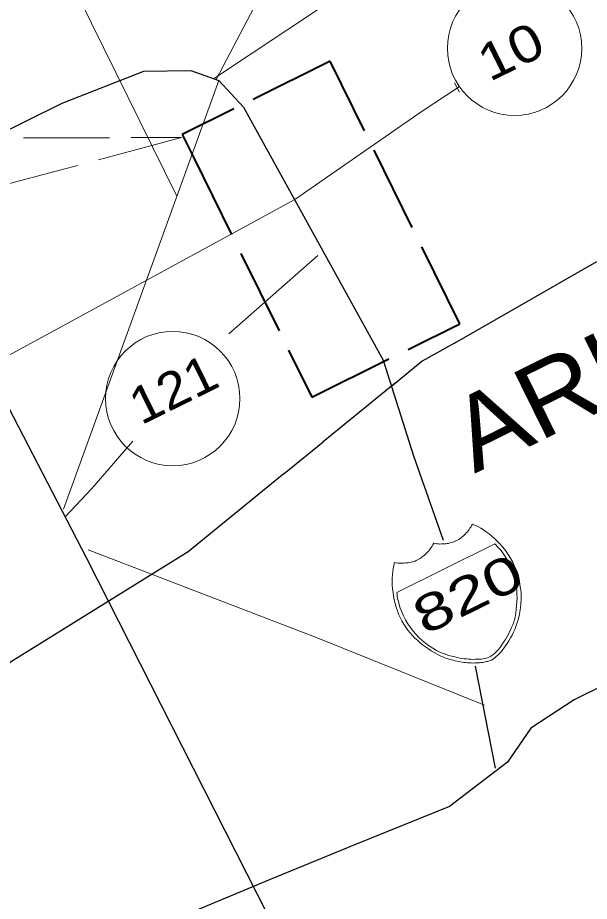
# Model space of a CAD drawing. Extents: x 2356606 to 2371222, y 6973096 to 6982644.
# Drawn here: x 2370898 to 2370977.6, y 6980347 to 6980470.1 of the extents above; entities that cross this region are included whole.
import ezdxf

# ---------------------------------------------------------------- set-up
doc = ezdxf.new("R2010")
doc.units = 0
doc.header["$LTSCALE"] = 2
doc.linetypes.add('LONG_DASHED', pattern=[7.5, 6, -1.5])
doc.layers.add('62', color=7, linetype='Continuous', lineweight=13)
doc.layers.add('63', color=7, linetype='Continuous', lineweight=13)

msp = doc.modelspace()

# ---------------------------------------------------------------- linework, layer by layer
at = {"layer": '62'}
for p, q in [((2370920.14, 6980445.229), (2370900.731, 6980484.556)), ((2370925.98, 6980461.31), (2370904.323, 6980401.619)), ((2370954.344, 6980457.069), (2370959.496, 6980460.463)), ((2370958.814, 6980460.982), (2370959.542, 6980459.711)), ((2370932.403, 6980430.45), (2370939.761, 6980436.945)), ((2370927.387, 6980426.022), (2370932.403, 6980430.45)), ((2370908.276, 6980404.496), (2370913.994, 6980411.055)), ((2370908.276, 6980404.496), (2370904.581, 6980400.541))]:
    msp.add_line(p, q, dxfattribs=at)
at = {"layer": '62', "lineweight": 25}
for p, q in [((2370925.98, 6980461.31), (2370929.431, 6980457.621)), ((2370929.431, 6980457.62), (2370948.893, 6980422.357)), ((2370958.804, 6980424.741), (2370978.671, 6980436.103)), ((2370950.577, 6980419.149), (2370940.532, 6980410.978)), ((2370935.107, 6980406.569), (2370940.532, 6980410.978)), ((2370961.725, 6980379.732), (2370964.509, 6980365.5))]:
    msp.add_line(p, q, dxfattribs=at)
at = {"layer": '62'}
for points in [[(2370938.756, 6980487.894), (2370934.235, 6980477.93), (2370925.608, 6980461.455)], [(2370925.246, 6980461.577), (2370940.846, 6980471.91), (2370955.63, 6980481.415)], [(2370954.344, 6980457.069), (2370936.581, 6980444.761), (2370894.075, 6980421.624), (2370888.003, 6980417.247)], [(2370956.789, 6980396.747), (2370957.012, 6980396.756), (2370957.214, 6980396.753), (2370957.405, 6980396.774), (2370957.626, 6980396.782), (2370957.807, 6980396.822), (2370957.999, 6980396.84), (2370958.202, 6980396.89), (2370958.371, 6980396.949), (2370958.572, 6980396.998), (2370958.753, 6980397.038), (2370958.936, 6980397.128), (2370959.117, 6980397.217), (2370959.259, 6980397.287), (2370959.44, 6980397.377), (2370959.601, 6980397.507), (2370959.743, 6980397.627), (2370959.897, 6980397.726), (2370960.055, 6980397.857), (2370960.189, 6980397.997), (2370960.329, 6980398.116), (2370960.472, 6980398.287), (2370960.623, 6980398.438), (2370960.725, 6980398.588), (2370960.866, 6980398.758), (2370960.978, 6980398.939), (2370961.098, 6980399.101), (2370961.219, 6980399.308), (2370961.342, 6980399.52), (2370961.706, 6980399.348), (2370962.067, 6980399.173), (2370962.478, 6980398.95), (2370962.847, 6980398.707), (2370963.23, 6980398.442), (2370963.641, 6980398.17), (2370964.022, 6980397.855), (2370964.382, 6980397.532), (2370964.772, 6980397.149), (2370965.133, 6980396.774), (2370965.492, 6980396.398), (2370965.823, 6980395.986), (2370966.133, 6980395.561), (2370966.422, 6980395.125), (2370966.682, 6980394.702), (2370966.943, 6980394.228), (2370967.159, 6980393.735), (2370967.378, 6980393.188), (2370967.568, 6980392.654), (2370967.737, 6980392.162), (2370967.874, 6980391.627), (2370967.951, 6980391.064), (2370968.03, 6980390.551), (2370968.097, 6980390.005), (2370968.134, 6980389.473), (2370968.112, 6980388.907), (2370968.088, 6980388.395), (2370968.037, 6980387.84), (2370967.932, 6980387.287), (2370967.839, 6980386.764), (2370967.684, 6980386.213), (2370967.524, 6980385.679), (2370967.367, 6980385.278), (2370967.226, 6980384.855), (2370967.052, 6980384.444), (2370966.868, 6980384.052), (2370966.634, 6980383.66), (2370966.402, 6980383.271), (2370966.179, 6980382.909), (2370965.936, 6980382.539), (2370965.712, 6980382.228), (2370965.469, 6980381.907), (2370965.196, 6980381.597), (2370964.933, 6980381.316), (2370964.699, 6980381.127), (2370964.439, 6980380.895), (2370964.196, 6980380.726), (2370963.962, 6980380.586)], [(2370963.962, 6980380.586), (2370963.793, 6980380.527), (2370963.651, 6980380.457), (2370963.458, 6980380.388), (2370963.299, 6980380.357), (2370963.117, 6980380.32), (2370962.936, 6980380.278), (2370962.724, 6980380.252), (2370962.51, 6980380.221), (2370962.293, 6980380.213), (2370962.08, 6980380.184), (2370961.827, 6980380.185), (2370961.628, 6980380.186), (2370961.385, 6980380.168), (2370961.153, 6980380.177), (2370960.892, 6980380.2), (2370960.661, 6980380.212), (2370960.399, 6980380.233), (2370960.138, 6980380.254), (2370959.888, 6980380.305), (2370959.664, 6980380.347), (2370959.424, 6980380.378), (2370959.143, 6980380.44), (2370958.89, 6980380.492), (2370958.68, 6980380.564), (2370958.408, 6980380.605), (2370958.197, 6980380.676), (2370957.936, 6980380.748), (2370957.726, 6980380.818), (2370957.484, 6980380.902), (2370957.275, 6980380.972), (2370957.072, 6980381.075), (2370956.851, 6980381.167), (2370956.419, 6980381.378), (2370955.977, 6980381.613), (2370955.575, 6980381.868), (2370955.195, 6980382.132), (2370954.784, 6980382.404), (2370954.371, 6980382.68), (2370954.02, 6980382.984), (2370953.652, 6980383.328), (2370953.301, 6980383.632), (2370952.961, 6980384.018), (2370952.65, 6980384.391), (2370952.341, 6980384.764), (2370952.039, 6980385.169), (2370951.781, 6980385.591), (2370951.502, 6980386.057), (2370951.261, 6980386.491), (2370951.043, 6980386.983), (2370950.865, 6980387.448), (2370950.697, 6980387.941), (2370950.568, 6980388.457), (2370950.422, 6980388.96), (2370950.343, 6980389.472), (2370950.263, 6980389.986), (2370950.178, 6980390.522), (2370950.16, 6980391.014), (2370950.142, 6980391.507), (2370950.152, 6980391.988), (2370950.196, 6980392.463), (2370950.249, 6980392.916), (2370950.281, 6980393.358), (2370950.386, 6980393.76), (2370950.468, 6980394.153), (2370950.709, 6980394.122), (2370950.95, 6980394.09), (2370951.152, 6980394.087), (2370951.362, 6980394.069), (2370951.583, 6980394.077), (2370951.785, 6980394.076), (2370951.998, 6980394.105), (2370952.219, 6980394.114), (2370952.38, 6980394.143), (2370952.591, 6980394.173), (2370952.773, 6980394.211), (2370952.962, 6980394.28), (2370953.165, 6980394.33), (2370953.347, 6980394.367), (2370953.507, 6980394.449), (2370953.691, 6980394.537), (2370953.852, 6980394.619), (2370954.033, 6980394.708), (2370954.176, 6980394.829), (2370954.337, 6980394.956), (2370954.468, 6980395.048), (2370954.629, 6980395.176), (2370954.78, 6980395.327), (2370954.943, 6980395.458), (2370955.043, 6980395.608), (2370955.195, 6980395.76), (2370955.337, 6980395.929), (2370955.459, 6980396.09), (2370955.573, 6980396.269), (2370955.712, 6980396.44), (2370955.796, 6980396.631), (2370955.935, 6980396.851), (2370956.136, 6980396.8), (2370956.357, 6980396.759), (2370956.578, 6980396.767), (2370956.789, 6980396.747)], [(2370962.995, 6980374.312), (2370939.686, 6980383.663), (2370907.798, 6980395.952)]]:
    msp.add_lwpolyline(points, dxfattribs=at)
at = {"layer": '62', "linetype": 'LONG_DASHED', "lineweight": 40}
msp.add_lwpolyline([(2370922.432, 6980450.654), (2370938.933, 6980417.218), (2370959.577, 6980427.404), (2370941.512, 6980464.007), (2370920.869, 6980453.821)], close=True, dxfattribs=at)
at = {"layer": '62', "lineweight": 25}
for points in [[(2370836.799, 6980393.483), (2370842.869, 6980403.757), (2370853.379, 6980414.24), (2370860.236, 6980422.918), (2370867.185, 6980431.465), (2370875.952, 6980441.111), (2370880.901, 6980446.691), (2370889.861, 6980451.112), (2370904.166, 6980458.172), (2370915.531, 6980462.603), (2370922.103, 6980462.709), (2370925.98, 6980461.31)], [(2370885.051, 6980438.124), (2370907.53, 6980394.764), (2370932.824, 6980345.045), (2370969.992, 6980283.97), (2370998.654, 6980263.059)], [(2370958.804, 6980424.741), (2370954.315, 6980422.2), (2370950.041, 6980418.709)], [(2370948.893, 6980422.358), (2370953.121, 6980409.011), (2370957.257, 6980397.276)], [(2370935.107, 6980406.569), (2370921.734, 6980395.679), (2370896.929, 6980380.299), (2370879.573, 6980365.436), (2370873.619, 6980362.044)], [(2371011.483, 6980396.661), (2371005.138, 6980391.825), (2370996.569, 6980386.616), (2370984.445, 6980379.452), (2370975.486, 6980375.033), (2370969.457, 6980371.078), (2370966.224, 6980366.347), (2370958.11, 6980360.159), (2370945.05, 6980354.893), (2370933.131, 6980350.014), (2370920.141, 6980344.556), (2370901.53, 6980332.234), (2370881.498, 6980325.485), (2370864.621, 6980321.497), (2370853.225, 6980321.969), (2370844.613, 6980332.451), (2370838.758, 6980344.313), (2370834.175, 6980349.329), (2370834.503, 6980359.904)]]:
    msp.add_lwpolyline(points, dxfattribs=at)
at = {"layer": '62', "linetype": 'LONG_DASHED'}
for points in [[(2370853.763, 6980453.224), (2370920.786, 6980453.379), (2370861.241, 6980437.463)], [(2370853.763, 6980453.224), (2370920.786, 6980453.379), (2370861.241, 6980437.463), (2370853.763, 6980453.224)]]:
    msp.add_lwpolyline(points, close=True, dxfattribs=at)
at = {"layer": '62'}
msp.add_lwpolyline([(2370964.439, 6980396.757), (2370950.778, 6980390.014), (2370950.814, 6980389.783), (2370950.843, 6980389.471), (2370950.904, 6980389.149), (2370951.023, 6980388.755), (2370951.121, 6980388.303), (2370951.248, 6980387.787), (2370951.467, 6980387.295), (2370951.726, 6980386.72), (2370952.016, 6980386.183), (2370952.323, 6980385.61), (2370952.694, 6980385.115), (2370953.064, 6980384.619), (2370953.474, 6980384.145), (2370953.875, 6980383.74), (2370954.344, 6980383.295), (2370954.807, 6980382.922), (2370955.28, 6980382.574), (2370955.788, 6980382.248), (2370956.325, 6980381.933), (2370956.866, 6980381.651), (2370957.447, 6980381.436), (2370958.05, 6980381.232), (2370958.651, 6980381.076), (2370959.275, 6980380.932), (2370959.546, 6980380.84), (2370959.859, 6980380.819), (2370960.191, 6980380.757), (2370960.503, 6980380.736), (2370960.794, 6980380.702), (2370961.105, 6980380.681), (2370961.407, 6980380.68), (2370961.73, 6980380.689), (2370962.002, 6980380.698), (2370962.273, 6980380.706), (2370962.565, 6980380.723), (2370962.827, 6980380.753), (2370963.08, 6980380.802), (2370963.3, 6980380.862), (2370963.53, 6980380.951), (2370963.745, 6980381.031), (2370964.007, 6980381.208), (2370964.329, 6980381.42), (2370964.573, 6980381.69), (2370964.897, 6980382.001), (2370965.15, 6980382.3), (2370965.413, 6980382.681), (2370965.677, 6980383.063), (2370965.92, 6980383.435), (2370966.185, 6980383.864), (2370966.378, 6980384.287), (2370966.581, 6980384.689), (2370966.775, 6980385.109), (2370966.957, 6980385.5), (2370967.079, 6980385.862), (2370967.191, 6980386.245), (2370967.265, 6980386.556), (2370967.357, 6980387.129), (2370967.441, 6980387.674), (2370967.484, 6980388.197), (2370967.517, 6980388.739), (2370967.549, 6980389.235), (2370967.531, 6980389.728), (2370967.523, 6980390.201), (2370967.465, 6980390.674), (2370967.408, 6980391.148), (2370967.329, 6980391.56), (2370967.231, 6980392.012), (2370967.083, 6980392.415), (2370966.952, 6980392.83), (2370966.805, 6980393.232), (2370966.636, 6980393.625), (2370966.476, 6980393.998), (2370966.177, 6980394.555), (2370965.898, 6980395.02), (2370965.589, 6980395.443), (2370965.348, 6980395.826), (2370965.071, 6980396.141), (2370964.829, 6980396.372), (2370964.619, 6980396.594)], close=True, dxfattribs=at)
for centre in [(2370967.199, 6980465.817), (2370919.564, 6980417.013)]:
    msp.add_circle(centre, 9.364, dxfattribs=at)
at = {"layer": '63'}
for p, q in [((2370920.14, 6980445.229), (2370900.731, 6980484.556)), ((2370925.98, 6980461.31), (2370904.323, 6980401.619)), ((2370954.344, 6980457.069), (2370959.496, 6980460.463)), ((2370958.814, 6980460.982), (2370959.542, 6980459.711)), ((2370932.403, 6980430.45), (2370939.761, 6980436.945)), ((2370927.387, 6980426.022), (2370932.403, 6980430.45)), ((2370908.276, 6980404.496), (2370913.994, 6980411.055)), ((2370908.276, 6980404.496), (2370904.581, 6980400.541))]:
    msp.add_line(p, q, dxfattribs=at)
at = {"layer": '63', "lineweight": 25}
for p, q in [((2370925.98, 6980461.31), (2370929.431, 6980457.621)), ((2370929.431, 6980457.62), (2370948.893, 6980422.357)), ((2370958.804, 6980424.741), (2370978.671, 6980436.103)), ((2370950.577, 6980419.149), (2370940.532, 6980410.978)), ((2370935.107, 6980406.569), (2370940.532, 6980410.978)), ((2370961.725, 6980379.732), (2370964.509, 6980365.5))]:
    msp.add_line(p, q, dxfattribs=at)
at = {"layer": '63'}
for points in [[(2370938.756, 6980487.894), (2370934.235, 6980477.93), (2370925.608, 6980461.455)], [(2370925.246, 6980461.577), (2370940.846, 6980471.91), (2370955.63, 6980481.415)], [(2370954.344, 6980457.069), (2370936.581, 6980444.761), (2370894.075, 6980421.624), (2370888.003, 6980417.247)], [(2370956.789, 6980396.747), (2370957.012, 6980396.756), (2370957.214, 6980396.753), (2370957.405, 6980396.774), (2370957.626, 6980396.782), (2370957.807, 6980396.822), (2370957.999, 6980396.84), (2370958.202, 6980396.89), (2370958.371, 6980396.949), (2370958.572, 6980396.998), (2370958.753, 6980397.038), (2370958.936, 6980397.128), (2370959.117, 6980397.217), (2370959.259, 6980397.287), (2370959.44, 6980397.377), (2370959.601, 6980397.507), (2370959.743, 6980397.627), (2370959.897, 6980397.726), (2370960.055, 6980397.857), (2370960.189, 6980397.997), (2370960.329, 6980398.116), (2370960.472, 6980398.287), (2370960.623, 6980398.438), (2370960.725, 6980398.588), (2370960.866, 6980398.758), (2370960.978, 6980398.939), (2370961.098, 6980399.101), (2370961.219, 6980399.308), (2370961.342, 6980399.52), (2370961.706, 6980399.348), (2370962.067, 6980399.173), (2370962.478, 6980398.95), (2370962.847, 6980398.707), (2370963.23, 6980398.442), (2370963.641, 6980398.17), (2370964.022, 6980397.855), (2370964.382, 6980397.532), (2370964.772, 6980397.149), (2370965.133, 6980396.774), (2370965.492, 6980396.398), (2370965.823, 6980395.986), (2370966.133, 6980395.561), (2370966.422, 6980395.125), (2370966.682, 6980394.702), (2370966.943, 6980394.228), (2370967.159, 6980393.735), (2370967.378, 6980393.188), (2370967.568, 6980392.654), (2370967.737, 6980392.162), (2370967.874, 6980391.627), (2370967.951, 6980391.064), (2370968.03, 6980390.551), (2370968.097, 6980390.005), (2370968.134, 6980389.473), (2370968.112, 6980388.907), (2370968.088, 6980388.395), (2370968.037, 6980387.84), (2370967.932, 6980387.287), (2370967.839, 6980386.764), (2370967.684, 6980386.213), (2370967.524, 6980385.679), (2370967.367, 6980385.278), (2370967.226, 6980384.855), (2370967.052, 6980384.444), (2370966.868, 6980384.052), (2370966.634, 6980383.66), (2370966.402, 6980383.271), (2370966.179, 6980382.909), (2370965.936, 6980382.539), (2370965.712, 6980382.228), (2370965.469, 6980381.907), (2370965.196, 6980381.597), (2370964.933, 6980381.316), (2370964.699, 6980381.127), (2370964.439, 6980380.895), (2370964.196, 6980380.726), (2370963.962, 6980380.586)], [(2370963.962, 6980380.586), (2370963.793, 6980380.527), (2370963.651, 6980380.457), (2370963.458, 6980380.388), (2370963.299, 6980380.357), (2370963.117, 6980380.32), (2370962.936, 6980380.278), (2370962.724, 6980380.252), (2370962.51, 6980380.221), (2370962.293, 6980380.213), (2370962.08, 6980380.184), (2370961.827, 6980380.185), (2370961.628, 6980380.186), (2370961.385, 6980380.168), (2370961.153, 6980380.177), (2370960.892, 6980380.2), (2370960.661, 6980380.212), (2370960.399, 6980380.233), (2370960.138, 6980380.254), (2370959.888, 6980380.305), (2370959.664, 6980380.347), (2370959.424, 6980380.378), (2370959.143, 6980380.44), (2370958.89, 6980380.492), (2370958.68, 6980380.564), (2370958.408, 6980380.605), (2370958.197, 6980380.676), (2370957.936, 6980380.748), (2370957.726, 6980380.818), (2370957.484, 6980380.902), (2370957.275, 6980380.972), (2370957.072, 6980381.075), (2370956.851, 6980381.167), (2370956.419, 6980381.378), (2370955.977, 6980381.613), (2370955.575, 6980381.868), (2370955.195, 6980382.132), (2370954.784, 6980382.404), (2370954.371, 6980382.68), (2370954.02, 6980382.984), (2370953.652, 6980383.328), (2370953.301, 6980383.632), (2370952.961, 6980384.018), (2370952.65, 6980384.391), (2370952.341, 6980384.764), (2370952.039, 6980385.169), (2370951.781, 6980385.591), (2370951.502, 6980386.057), (2370951.261, 6980386.491), (2370951.043, 6980386.983), (2370950.865, 6980387.448), (2370950.697, 6980387.941), (2370950.568, 6980388.457), (2370950.422, 6980388.96), (2370950.343, 6980389.472), (2370950.263, 6980389.986), (2370950.178, 6980390.522), (2370950.16, 6980391.014), (2370950.142, 6980391.507), (2370950.152, 6980391.988), (2370950.196, 6980392.463), (2370950.249, 6980392.916), (2370950.281, 6980393.358), (2370950.386, 6980393.76), (2370950.468, 6980394.153), (2370950.709, 6980394.122), (2370950.95, 6980394.09), (2370951.152, 6980394.087), (2370951.362, 6980394.069), (2370951.583, 6980394.077), (2370951.785, 6980394.076), (2370951.998, 6980394.105), (2370952.219, 6980394.114), (2370952.38, 6980394.143), (2370952.591, 6980394.173), (2370952.773, 6980394.211), (2370952.962, 6980394.28), (2370953.165, 6980394.33), (2370953.347, 6980394.367), (2370953.507, 6980394.449), (2370953.691, 6980394.537), (2370953.852, 6980394.619), (2370954.033, 6980394.708), (2370954.176, 6980394.829), (2370954.337, 6980394.956), (2370954.468, 6980395.048), (2370954.629, 6980395.176), (2370954.78, 6980395.327), (2370954.943, 6980395.458), (2370955.043, 6980395.608), (2370955.195, 6980395.76), (2370955.337, 6980395.929), (2370955.459, 6980396.09), (2370955.573, 6980396.269), (2370955.712, 6980396.44), (2370955.796, 6980396.631), (2370955.935, 6980396.851), (2370956.136, 6980396.8), (2370956.357, 6980396.759), (2370956.578, 6980396.767), (2370956.789, 6980396.747)], [(2370962.995, 6980374.312), (2370939.686, 6980383.663), (2370907.798, 6980395.952)]]:
    msp.add_lwpolyline(points, dxfattribs=at)
at = {"layer": '63', "linetype": 'LONG_DASHED', "lineweight": 40}
msp.add_lwpolyline([(2370922.432, 6980450.654), (2370938.933, 6980417.218), (2370959.577, 6980427.404), (2370941.512, 6980464.007), (2370920.869, 6980453.821)], close=True, dxfattribs=at)
at = {"layer": '63', "lineweight": 25}
for points in [[(2370836.799, 6980393.483), (2370842.869, 6980403.757), (2370853.379, 6980414.24), (2370860.236, 6980422.918), (2370867.185, 6980431.465), (2370875.952, 6980441.111), (2370880.901, 6980446.691), (2370889.861, 6980451.112), (2370904.166, 6980458.172), (2370915.531, 6980462.603), (2370922.103, 6980462.709), (2370925.98, 6980461.31)], [(2370885.051, 6980438.124), (2370907.53, 6980394.764), (2370932.824, 6980345.045), (2370969.992, 6980283.97), (2370998.654, 6980263.059)], [(2370958.804, 6980424.741), (2370954.315, 6980422.2), (2370950.041, 6980418.709)], [(2370948.893, 6980422.358), (2370953.121, 6980409.011), (2370957.257, 6980397.276)], [(2370935.107, 6980406.569), (2370921.734, 6980395.679), (2370896.929, 6980380.299), (2370879.573, 6980365.436), (2370873.619, 6980362.044)], [(2371011.483, 6980396.661), (2371005.138, 6980391.825), (2370996.569, 6980386.616), (2370984.445, 6980379.452), (2370975.486, 6980375.033), (2370969.457, 6980371.078), (2370966.224, 6980366.347), (2370958.11, 6980360.159), (2370945.05, 6980354.893), (2370933.131, 6980350.014), (2370920.141, 6980344.556), (2370901.53, 6980332.234), (2370881.498, 6980325.485), (2370864.621, 6980321.497), (2370853.225, 6980321.969), (2370844.613, 6980332.451), (2370838.758, 6980344.313), (2370834.175, 6980349.329), (2370834.503, 6980359.904)]]:
    msp.add_lwpolyline(points, dxfattribs=at)
at = {"layer": '63', "linetype": 'LONG_DASHED'}
for points in [[(2370853.763, 6980453.224), (2370920.786, 6980453.379), (2370861.241, 6980437.463)], [(2370853.763, 6980453.224), (2370920.786, 6980453.379), (2370861.241, 6980437.463), (2370853.763, 6980453.224)]]:
    msp.add_lwpolyline(points, close=True, dxfattribs=at)
at = {"layer": '63'}
msp.add_lwpolyline([(2370964.439, 6980396.757), (2370950.778, 6980390.014), (2370950.814, 6980389.783), (2370950.843, 6980389.471), (2370950.904, 6980389.149), (2370951.023, 6980388.755), (2370951.121, 6980388.303), (2370951.248, 6980387.787), (2370951.467, 6980387.295), (2370951.726, 6980386.72), (2370952.016, 6980386.183), (2370952.323, 6980385.61), (2370952.694, 6980385.115), (2370953.064, 6980384.619), (2370953.474, 6980384.145), (2370953.875, 6980383.74), (2370954.344, 6980383.295), (2370954.807, 6980382.922), (2370955.28, 6980382.574), (2370955.788, 6980382.248), (2370956.325, 6980381.933), (2370956.866, 6980381.651), (2370957.447, 6980381.436), (2370958.05, 6980381.232), (2370958.651, 6980381.076), (2370959.275, 6980380.932), (2370959.546, 6980380.84), (2370959.859, 6980380.819), (2370960.191, 6980380.757), (2370960.503, 6980380.736), (2370960.794, 6980380.702), (2370961.105, 6980380.681), (2370961.407, 6980380.68), (2370961.73, 6980380.689), (2370962.002, 6980380.698), (2370962.273, 6980380.706), (2370962.565, 6980380.723), (2370962.827, 6980380.753), (2370963.08, 6980380.802), (2370963.3, 6980380.862), (2370963.53, 6980380.951), (2370963.745, 6980381.031), (2370964.007, 6980381.208), (2370964.329, 6980381.42), (2370964.573, 6980381.69), (2370964.897, 6980382.001), (2370965.15, 6980382.3), (2370965.413, 6980382.681), (2370965.677, 6980383.063), (2370965.92, 6980383.435), (2370966.185, 6980383.864), (2370966.378, 6980384.287), (2370966.581, 6980384.689), (2370966.775, 6980385.109), (2370966.957, 6980385.5), (2370967.079, 6980385.862), (2370967.191, 6980386.245), (2370967.265, 6980386.556), (2370967.357, 6980387.129), (2370967.441, 6980387.674), (2370967.484, 6980388.197), (2370967.517, 6980388.739), (2370967.549, 6980389.235), (2370967.531, 6980389.728), (2370967.523, 6980390.201), (2370967.465, 6980390.674), (2370967.408, 6980391.148), (2370967.329, 6980391.56), (2370967.231, 6980392.012), (2370967.083, 6980392.415), (2370966.952, 6980392.83), (2370966.805, 6980393.232), (2370966.636, 6980393.625), (2370966.476, 6980393.998), (2370966.177, 6980394.555), (2370965.898, 6980395.02), (2370965.589, 6980395.443), (2370965.348, 6980395.826), (2370965.071, 6980396.141), (2370964.829, 6980396.372), (2370964.619, 6980396.594)], close=True, dxfattribs=at)
for centre in [(2370967.199, 6980465.817), (2370919.564, 6980417.013)]:
    msp.add_circle(centre, 9.364, dxfattribs=at)

# ---------------------------------------------------------------- texts
at = {"layer": '62'}
for s, height, width, p in [('10', 5.099, 1.2, (2370963.705, 6980461.086)), ('ARLINGTON', 10.21, 1.1, (2370961.602, 6980406.523)), ('121', 5.099, 1.1, (2370915.164, 6980413.266)), ('820', 5.099, 1.4, (2370954.681, 6980383.987))]:
    msp.add_text(s, height=height, rotation=26.268, dxfattribs=dict(at, width=width)).set_placement(p)
at = {"layer": '63'}
for s, height, width, p in [('10', 5.099, 1.2, (2370963.705, 6980461.086)), ('ARLINGTON', 10.21, 1.1, (2370961.602, 6980406.523)), ('121', 5.099, 1.1, (2370915.164, 6980413.266)), ('820', 5.099, 1.4, (2370954.681, 6980383.987))]:
    msp.add_text(s, height=height, rotation=26.268, dxfattribs=dict(at, width=width)).set_placement(p)

doc.saveas('drawing.dxf')
